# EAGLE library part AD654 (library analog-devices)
Low Cost Monolithic Voltage-to-Frequency Converter
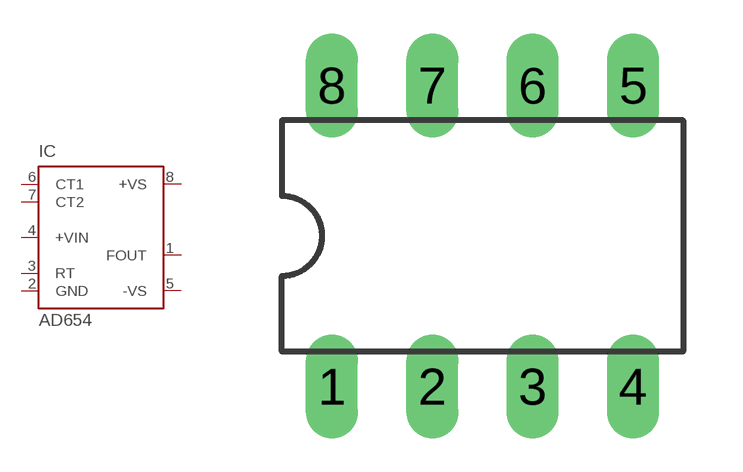
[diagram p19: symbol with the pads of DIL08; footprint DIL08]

Designator prefix IC

## AD654P (MF: ALTERA CORPORATION; MPN: AD654JNZ/+; OC_FARNELL: 9605053; OC_NEWARK: 59K4466)  [DIL08]
1  FOUT  oc
2  GND  pwr
3  RT  pas
4  +VIN  in
5  -VS  pwr
6  CT1  pas
7  CT2  pas
8  +VS  pwr

## Footprint DIL08 (pad centres in mm)
Dual In Line Package
drill 0.813 long: 1 -3.81,-3.81; 2 -1.27,-3.81; 3 1.27,-3.81; 4 3.81,-3.81; 5 3.81,3.81; 6 1.27,3.81; 7 -1.27,3.81; 8 -3.81,3.81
